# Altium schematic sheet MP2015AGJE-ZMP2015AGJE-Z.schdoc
size 127 x 101 mm
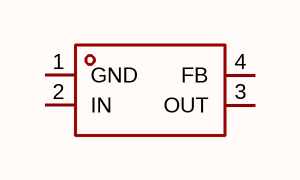
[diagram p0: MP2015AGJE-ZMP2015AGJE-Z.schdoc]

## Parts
U?  mp2015agje-z  [TSOT-23-4_L2.9-W1.6-P1.90-LS2.8-BL]  (value not drawn)

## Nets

Not connected (* = marked no-connect by the designer): U? 1(GND) 2(IN) 3(OUT) 4(FB)

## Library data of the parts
U? = mp2015agje-z: 输出极性:正极;工作电压:24V;输出电压:1.215V~15V;输出电流:100mA;电源纹波抑制比(PSRR):-;输出类型:可调;; Manufacturer: MPS(芯源); AddInBom: yes; Output Configuration: 正极; Voltage - Supply: 24V; Output Current: 100mA; Output Type: 可调; Number of Outputs: 1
